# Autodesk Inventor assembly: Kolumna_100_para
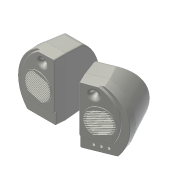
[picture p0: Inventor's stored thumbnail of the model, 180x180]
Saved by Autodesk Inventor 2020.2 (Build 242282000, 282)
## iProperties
Created: 2010-12
Part Number: Kolumna_100_para
Document SubType Name: Assembly
Designer: F.Stasiak
Manager: www.cadconsulting.pl
Company: Fabian Stasiak CAD Consulting
Author: F.Stasiak
Subject: Zbiór ćwiczeń. Autodesk Inventor 2020. Kurs podstawowy
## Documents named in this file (5)
- C:\2020_Kurs_podstawowy\R5 Części\Elementy\Kolumna_100_para.iam
- C:\2020_Kurs_podstawowy\R5 Części\Elementy\Tył_kolumny_100.ipt
- C:\2020_Kurs_podstawowy\R5 Części\Elementy\Front_kolumny_100.ipt
- C:\2020_Kurs_podstawowy\R5 Części\Elementy\Tył_kolumny_100_MIR.ipt
- C:\2020_Kurs_podstawowy\R5 Części\Elementy\Front_kolumny_100_MIR.ipt
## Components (4 placed, 4 different names)
1. Tył_kolumny_100:1 — Zestawiający:1, Zestawiający:2, Zestawiający:3, Równoległy:1
2. Front_kolumny_100:1 — Zestawiający:1, Zestawiający:2, Zestawiający:3
3. Tył_kolumny_100_MIR:1 — Zestawiający:4, Zestawiający:5, Zestawiający:6, Równoległy:1
4. Front_kolumny_100_MIR:1 — Zestawiający:4, Zestawiający:5, Zestawiający:6
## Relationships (7: Mate 6, Flush 1)
- Zestawiający:1 [Mate]: Tył_kolumny_100:1 ↔ Front_kolumny_100:1
- Zestawiający:2 [Mate]: Tył_kolumny_100:1 ↔ Front_kolumny_100:1
- Zestawiający:3 [Mate]: Tył_kolumny_100:1 ↔ Front_kolumny_100:1
- Zestawiający:4 [Mate]: Tył_kolumny_100_MIR:1 ↔ Front_kolumny_100_MIR:1
- Zestawiający:5 [Mate]: Tył_kolumny_100_MIR:1 ↔ Front_kolumny_100_MIR:1
- Zestawiający:6 [Mate]: Tył_kolumny_100_MIR:1 ↔ Front_kolumny_100_MIR:1
- Równoległy:1 [Flush]: Tył_kolumny_100:1 ↔ Tył_kolumny_100_MIR:1
